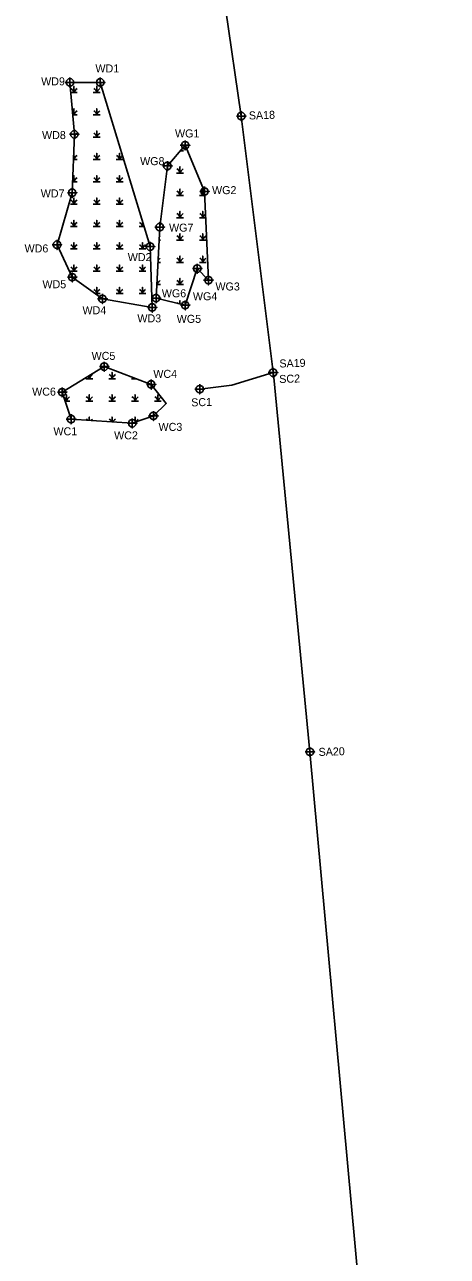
# Model space of a CAD drawing. Extents: x 1616941 to 1621864, y 896903 to 900301.
# Drawn here: x 1619806 to 1620070, y 897710 to 898479 of the extents above; entities that cross this region are included whole.
import ezdxf

# ---------------------------------------------------------------- set-up
doc = ezdxf.new("R2010")
doc.units = 0
for name, color, linetype in [('Exist Hydro Swamp or Marsh', 7, 'Continuous'), ('Sheet Block Revision CELL', 7, 'Continuous'), ('Sheet Layout Plan Border', 7, 'Continuous'), ('Sheet North Arrow Point CELL', 7, 'Continuous'), ('Sheet Plan CELL', 7, 'Continuous'), ('Sheet Plot Border Outside CELL', 7, 'Continuous'), ('Sheet Sticker Exception Certification CELL', 7, 'Continuous')]:
    doc.layers.add(name, color=color, linetype=linetype)

msp = doc.modelspace()

# ---------------------------------------------------------------- linework, layer by layer
at = {"layer": 'Exist Hydro Swamp or Marsh'}
for p, q in [((1619836.65, 898408.67), (1619838.56, 898408.67)), ((1619862.86, 898408.67), (1619863.36, 898408.67)), ((1619903.05, 898400.28), (1619904.89, 898400.28)), ((1619889.69, 898344.5), (1619890.59, 898344.5)), ((1619888.96, 898330.55), (1619890.59, 898330.55))]:
    msp.add_line(p, q, dxfattribs=at)
for points in [[(1619834.55, 898436.56), (1619836.41, 898436.56), (1619836.41, 898440.5), (1619836.41, 898436.56), (1619838.56, 898436.56)], [(1619848.56, 898436.56), (1619850.71, 898436.56), (1619850.71, 898440.5), (1619850.71, 898436.56), (1619852.86, 898436.56)], [(1619835.71, 898422.61), (1619836.41, 898422.61), (1619836.41, 898426.56), (1619836.41, 898422.61), (1619838.56, 898422.61)], [(1619848.56, 898422.61), (1619850.71, 898422.61), (1619850.71, 898426.56), (1619850.71, 898422.61), (1619852.86, 898422.61)], [(1619848.56, 898408.67), (1619850.71, 898408.67), (1619850.71, 898412.61), (1619850.71, 898408.67), (1619852.86, 898408.67)], [(1619836.13, 898394.72), (1619836.41, 898394.72), (1619836.41, 898398.67), (1619836.41, 898394.72), (1619838.56, 898394.72)], [(1619848.56, 898394.72), (1619850.71, 898394.72), (1619850.71, 898398.67), (1619850.71, 898394.72), (1619852.86, 898394.72)], [(1619862.86, 898394.72), (1619865.01, 898394.72), (1619865.01, 898398.67), (1619865.01, 898394.72), (1619867.16, 898394.72)], [(1619835.62, 898380.78), (1619836.41, 898380.78), (1619836.41, 898384.72), (1619836.41, 898380.78), (1619838.56, 898380.78)], [(1619848.56, 898380.78), (1619850.71, 898380.78), (1619850.71, 898384.72), (1619850.71, 898380.78), (1619852.86, 898380.78)], [(1619862.86, 898380.78), (1619865.01, 898380.78), (1619865.01, 898384.72), (1619865.01, 898380.78), (1619867.16, 898380.78)], [(1619900.59, 898386.33), (1619902.74, 898386.33), (1619902.74, 898390.28), (1619902.74, 898386.33), (1619904.89, 898386.33)], [(1619900.59, 898372.39), (1619902.74, 898372.39), (1619902.74, 898376.33), (1619902.74, 898372.39), (1619904.89, 898372.39)], [(1619914.89, 898372.39), (1619917.04, 898372.39), (1619917.04, 898376.33), (1619917.04, 898372.39), (1619918.21, 898372.39)], [(1619834.26, 898366.83), (1619836.41, 898366.83), (1619836.41, 898370.78), (1619836.41, 898366.83), (1619838.56, 898366.83)], [(1619848.56, 898366.83), (1619850.71, 898366.83), (1619850.71, 898370.78), (1619850.71, 898366.83), (1619852.86, 898366.83)], [(1619862.86, 898366.83), (1619865.01, 898366.83), (1619865.01, 898370.78), (1619865.01, 898366.83), (1619867.16, 898366.83)], [(1619900.59, 898358.44), (1619902.74, 898358.44), (1619902.74, 898362.39), (1619902.74, 898358.44), (1619904.89, 898358.44)], [(1619914.89, 898358.44), (1619917.04, 898358.44), (1619917.04, 898362.39), (1619917.04, 898358.44), (1619918.83, 898358.44)], [(1619834.26, 898352.89), (1619836.41, 898352.89), (1619836.41, 898356.83), (1619836.41, 898352.89), (1619838.56, 898352.89)], [(1619848.56, 898352.89), (1619850.71, 898352.89), (1619850.71, 898356.83), (1619850.71, 898352.89), (1619852.86, 898352.89)], [(1619862.86, 898352.89), (1619865.01, 898352.89), (1619865.01, 898356.83), (1619865.01, 898352.89), (1619867.16, 898352.89)], [(1619877.16, 898352.89), (1619879.31, 898352.89), (1619879.31, 898356.11)], [(1619879.31, 898356.11), (1619879.31, 898352.89), (1619880.29, 898352.89)], [(1619900.59, 898344.5), (1619902.74, 898344.5), (1619902.74, 898348.44), (1619902.74, 898344.5), (1619904.89, 898344.5)], [(1619914.89, 898344.5), (1619917.04, 898344.5), (1619917.04, 898348.44), (1619917.04, 898344.5), (1619919.19, 898344.5)], [(1619834.26, 898338.94), (1619836.41, 898338.94), (1619836.41, 898342.89), (1619836.41, 898338.94), (1619838.56, 898338.94)], [(1619848.56, 898338.94), (1619850.71, 898338.94), (1619850.71, 898342.89), (1619850.71, 898338.94), (1619852.86, 898338.94)], [(1619862.86, 898338.94), (1619865.01, 898338.94), (1619865.01, 898342.89), (1619865.01, 898338.94), (1619867.16, 898338.94)], [(1619877.16, 898338.94), (1619879.31, 898338.94), (1619879.31, 898342.89), (1619879.31, 898338.94), (1619881.46, 898338.94)], [(1619834.26, 898325), (1619836.41, 898325), (1619836.41, 898328.94), (1619836.41, 898325), (1619838.56, 898325)], [(1619848.56, 898325), (1619850.71, 898325), (1619850.71, 898328.94), (1619850.71, 898325), (1619852.86, 898325)], [(1619862.86, 898325), (1619865.01, 898325), (1619865.01, 898328.94), (1619865.01, 898325), (1619867.16, 898325)], [(1619877.16, 898325), (1619879.31, 898325), (1619879.31, 898328.94), (1619879.31, 898325), (1619881.46, 898325)], [(1619900.59, 898330.55), (1619902.74, 898330.55), (1619902.74, 898334.5), (1619902.74, 898330.55), (1619904.89, 898330.55)], [(1619914.89, 898330.55), (1619917.04, 898330.55), (1619917.04, 898334.5), (1619917.04, 898330.55), (1619919.19, 898330.55)], [(1619849.71, 898311.05), (1619850.71, 898311.05), (1619850.71, 898315), (1619850.71, 898311.05), (1619852.86, 898311.05)], [(1619862.86, 898311.05), (1619865.01, 898311.05), (1619865.01, 898315), (1619865.01, 898311.05), (1619867.16, 898311.05)], [(1619877.16, 898311.05), (1619879.31, 898311.05), (1619879.31, 898315), (1619879.31, 898311.05), (1619881.46, 898311.05)], [(1619888.23, 898316.61), (1619888.44, 898316.61), (1619888.44, 898320.55), (1619888.44, 898316.61), (1619890.59, 898316.61)], [(1619900.59, 898316.61), (1619902.74, 898316.61), (1619902.74, 898320.55), (1619902.74, 898316.61), (1619904.89, 898316.61)], [(1619902.74, 898304.59), (1619902.74, 898306.61), (1619902.74, 898304.59)], [(1619843.91, 898257.85), (1619846.06, 898257.85), (1619846.06, 898259.7)], [(1619846.06, 898259.7), (1619846.06, 898257.85), (1619848.21, 898257.85)], [(1619858.21, 898257.85), (1619860.36, 898257.85), (1619860.36, 898261.8), (1619860.36, 898257.85), (1619862.51, 898257.85)], [(1619872.51, 898257.85), (1619874.66, 898257.85), (1619874.66, 898258.1)], [(1619874.66, 898258.1), (1619874.66, 898257.85), (1619875.32, 898257.85)], [(1619830.94, 898243.91), (1619831.76, 898243.91), (1619831.76, 898247.85), (1619831.76, 898243.91), (1619833.91, 898243.91)], [(1619843.91, 898243.91), (1619846.06, 898243.91), (1619846.06, 898247.85), (1619846.06, 898243.91), (1619848.21, 898243.91)], [(1619858.21, 898243.91), (1619860.36, 898243.91), (1619860.36, 898247.85), (1619860.36, 898243.91), (1619862.51, 898243.91)], [(1619872.51, 898243.91), (1619874.66, 898243.91), (1619874.66, 898247.85), (1619874.66, 898243.91), (1619876.81, 898243.91)], [(1619886.81, 898243.91), (1619888.96, 898243.91), (1619888.96, 898247.85), (1619888.96, 898243.91), (1619891.11, 898243.91)], [(1619846.06, 898231.84), (1619846.06, 898233.91), (1619846.06, 898231.84)], [(1619860.36, 898230.86), (1619860.36, 898233.91), (1619860.36, 898230.86)], [(1619874.66, 898231.58), (1619874.66, 898233.91), (1619874.66, 898231.58)]]:
    msp.add_lwpolyline(points, dxfattribs=at)
for centre, radius, start, end in [((1619833.34, 898436.33), 3.07, 4.14034, 67.53497), ((1619840.97, 898435.04), 4.81, 122.12745, 161.62219), ((1619847.64, 898436.33), 3.07, 4.14034, 67.53497), ((1619855.27, 898435.04), 4.81, 122.12745, 161.62219), ((1619833.34, 898422.39), 3.07, 4.14034, 44.10069), ((1619840.97, 898421.1), 4.81, 122.12745, 161.62219), ((1619847.64, 898422.39), 3.07, 4.14034, 67.53497), ((1619855.27, 898421.1), 4.81, 122.12745, 161.62219), ((1619840.97, 898407.15), 4.81, 122.12745, 153.42226), ((1619847.64, 898408.44), 3.07, 4.14034, 67.53497), ((1619855.27, 898407.15), 4.81, 122.12745, 161.62219), ((1619833.34, 898394.5), 3.07, 4.14034, 23.20165), ((1619840.97, 898393.21), 4.81, 122.12745, 161.62219), ((1619847.64, 898394.5), 3.07, 4.14034, 67.53497), ((1619855.27, 898393.21), 4.81, 122.12745, 161.62219), ((1619861.95, 898394.5), 3.07, 4.14034, 67.53497), ((1619869.57, 898393.21), 4.81, 124.50854, 161.62219), ((1619840.97, 898379.26), 4.81, 122.12745, 161.62219), ((1619847.64, 898380.55), 3.07, 4.14034, 67.53497), ((1619855.27, 898379.26), 4.81, 122.12745, 161.62219), ((1619861.95, 898380.55), 3.07, 4.14034, 67.53497), ((1619869.57, 898379.26), 4.81, 122.12745, 161.62219), ((1619899.67, 898386.11), 3.07, 4.14034, 67.53497), ((1619907.3, 898384.82), 4.81, 122.12745, 161.62219), ((1619833.34, 898380.55), 3.07, 4.14034, 40.48348), ((1619833.34, 898366.61), 3.07, 4.14034, 67.53497), ((1619840.97, 898365.32), 4.81, 122.12745, 161.62219), ((1619847.64, 898366.61), 3.07, 4.14034, 67.53497), ((1619855.27, 898365.32), 4.81, 122.12745, 161.62219), ((1619861.95, 898366.61), 3.07, 4.14034, 67.53497), ((1619869.57, 898365.32), 4.81, 122.12745, 161.62219), ((1619899.67, 898372.17), 3.07, 4.14034, 67.53497), ((1619907.3, 898370.87), 4.81, 122.12745, 161.62219), ((1619913.97, 898372.17), 3.07, 4.14034, 67.53497), ((1619921.6, 898370.87), 4.81, 136.20709, 161.62219), ((1619899.67, 898358.22), 3.07, 4.14034, 67.53497), ((1619907.3, 898356.93), 4.81, 122.12745, 161.62219), ((1619913.97, 898358.22), 3.07, 4.14034, 67.53497), ((1619921.6, 898356.93), 4.81, 126.67879, 161.62219), ((1619833.34, 898352.66), 3.07, 4.14034, 67.53497), ((1619840.97, 898351.37), 4.81, 122.12745, 161.62219), ((1619847.64, 898352.66), 3.07, 4.14034, 67.53497), ((1619855.27, 898351.37), 4.81, 122.12745, 161.62219), ((1619861.95, 898352.66), 3.07, 4.14034, 67.53497), ((1619869.57, 898351.37), 4.81, 122.12745, 161.62219), ((1619876.25, 898352.66), 3.07, 4.14034, 67.53497), ((1619883.87, 898351.37), 4.81, 145.30096, 161.62219), ((1619893, 898342.98), 4.81, 122.12745, 131.84472), ((1619899.67, 898344.27), 3.07, 4.14034, 67.53497), ((1619907.3, 898342.98), 4.81, 122.12745, 161.62219), ((1619913.97, 898344.27), 3.07, 4.14034, 67.53497), ((1619921.6, 898342.98), 4.81, 122.12745, 161.62219), ((1619833.34, 898338.72), 3.07, 4.14034, 67.53497), ((1619840.97, 898337.43), 4.81, 122.12745, 161.62219), ((1619847.64, 898338.72), 3.07, 4.14034, 67.53497), ((1619855.27, 898337.43), 4.81, 122.12745, 161.62219), ((1619861.95, 898338.72), 3.07, 4.14034, 67.53497), ((1619869.57, 898337.43), 4.81, 122.12745, 161.62219), ((1619876.25, 898338.72), 3.07, 4.14034, 67.53497), ((1619883.87, 898337.43), 4.81, 122.12745, 161.62219), ((1619893, 898329.04), 4.81, 122.12745, 145.88991), ((1619899.67, 898330.33), 3.07, 4.14034, 67.53497), ((1619907.3, 898329.04), 4.81, 122.12745, 161.62219), ((1619913.97, 898330.33), 3.07, 4.14034, 67.53497), ((1619921.6, 898329.04), 4.81, 122.12745, 161.62219), ((1619833.34, 898324.77), 3.07, 4.14034, 67.53497), ((1619840.97, 898323.48), 4.81, 122.12745, 161.62219), ((1619847.64, 898324.77), 3.07, 4.14034, 67.53497), ((1619855.27, 898323.48), 4.81, 122.12745, 161.62219), ((1619861.95, 898324.77), 3.07, 4.14034, 67.53497), ((1619869.57, 898323.48), 4.81, 122.12745, 161.62219), ((1619876.25, 898324.77), 3.07, 4.14034, 67.53497), ((1619883.87, 898323.48), 4.81, 122.12745, 161.62219), ((1619847.64, 898310.83), 3.07, 4.14034, 67.53497), ((1619855.27, 898309.54), 4.81, 122.12745, 161.62219), ((1619861.95, 898310.83), 3.07, 4.14034, 67.53497), ((1619869.57, 898309.54), 4.81, 122.12745, 161.62219), ((1619876.25, 898310.83), 3.07, 4.14034, 67.53497), ((1619883.87, 898309.54), 4.81, 122.12745, 161.62219), ((1619885.37, 898316.38), 3.07, 4.14034, 19.32546), ((1619893, 898315.09), 4.81, 122.12745, 161.62219), ((1619899.67, 898316.38), 3.07, 4.14034, 67.53497), ((1619907.3, 898315.09), 4.81, 122.12745, 161.62219), ((1619899.67, 898302.44), 3.07, 52.45987, 67.53497), ((1619907.3, 898301.15), 4.81, 122.12745, 138.14469), ((1619850.62, 898256.34), 4.81, 122.12745, 161.62219), ((1619857.29, 898257.63), 3.07, 4.14034, 67.53497), ((1619864.92, 898256.34), 4.81, 122.12745, 161.62219), ((1619842.99, 898257.63), 3.07, 4.14034, 34.65397), ((1619871.59, 898257.63), 3.07, 4.14034, 9.10063), ((1619879.22, 898256.34), 4.81, 158.80505, 161.62219), ((1619828.69, 898243.68), 3.07, 4.14034, 62.4002), ((1619836.32, 898242.39), 4.81, 122.12745, 161.62219), ((1619842.99, 898243.68), 3.07, 4.14034, 67.53497), ((1619850.62, 898242.39), 4.81, 122.12745, 161.62219), ((1619857.29, 898243.68), 3.07, 4.14034, 67.53497), ((1619864.92, 898242.39), 4.81, 122.12745, 161.62219), ((1619871.59, 898243.68), 3.07, 4.14034, 67.53497), ((1619879.22, 898242.39), 4.81, 122.12745, 161.62219), ((1619885.89, 898243.68), 3.07, 4.14034, 67.53497), ((1619893.52, 898242.39), 4.81, 122.12745, 161.62219), ((1619842.99, 898229.74), 3.07, 44.55953, 67.53497), ((1619850.62, 898228.45), 4.81, 122.12745, 136.35309), ((1619857.29, 898229.74), 3.07, 21.70782, 67.53497), ((1619864.92, 898228.45), 4.81, 122.12745, 150.18472), ((1619871.59, 898229.74), 3.07, 57.27491, 67.53497), ((1619879.22, 898228.45), 4.81, 122.12745, 149.27571)]:
    msp.add_arc(centre, radius, start, end, dxfattribs=at)
at = {"layer": 'Sheet Block Revision CELL'}
for points in [[(1619834.01, 898442.98), (1619852.94, 898442.98), (1619884.09, 898340.38), (1619885.39, 898302.37), (1619854.29, 898307.77), (1619835.37, 898321.29), (1619825.9, 898341.57), (1619835.37, 898374.02), (1619836.72, 898410.53)], [(1619905.99, 898403.72), (1619918.1, 898374.83), (1619920.58, 898319.43), (1619913.57, 898326.66), (1619906.02, 898303.8), (1619887.79, 898308.19), (1619890.11, 898352.57), (1619894.93, 898390.78)], [(1619834.69, 898232.61), (1619829.11, 898249.44), (1619855.45, 898265.4), (1619884.76, 898254.27), (1619894.23, 898242.45), (1619886.16, 898234.63), (1619872.92, 898230.01)]]:
    msp.add_lwpolyline(points, close=True, dxfattribs=at)
at = {"layer": 'Sheet North Arrow Point CELL'}
for points in [[(1619941.08, 898424.92), (1619941.08, 898418.92), (1619941.08, 898421.92), (1619944.08, 898421.92), (1619938.08, 898421.92)], [(1619960.99, 898264.64), (1619960.99, 898258.64), (1619960.99, 898261.64), (1619963.99, 898261.64), (1619957.99, 898261.64)], [(1619915.11, 898254.34), (1619915.11, 898248.34), (1619915.11, 898251.34), (1619918.11, 898251.34), (1619912.11, 898251.34)], [(1619984.05, 898027.72), (1619984.05, 898021.72), (1619984.05, 898024.72), (1619987.05, 898024.72), (1619981.05, 898024.72)]]:
    msp.add_lwpolyline(points, dxfattribs=at)
for centre in [(1619941.08, 898421.92), (1619960.99, 898261.64), (1619915.11, 898251.34), (1619984.05, 898024.72)]:
    msp.add_circle(centre, 2.34, dxfattribs=at)
at = {"layer": 'Sheet Plan CELL'}
for points in [[(1619834.01, 898445.98), (1619834.01, 898439.98), (1619834.01, 898442.98), (1619837.01, 898442.98), (1619831.01, 898442.98)], [(1619852.94, 898445.98), (1619852.94, 898439.98), (1619852.94, 898442.98), (1619855.94, 898442.98), (1619849.94, 898442.98)], [(1619836.72, 898413.53), (1619836.72, 898407.53), (1619836.72, 898410.53), (1619839.72, 898410.53), (1619833.72, 898410.53)], [(1619905.99, 898406.72), (1619905.99, 898400.72), (1619905.99, 898403.72), (1619908.99, 898403.72), (1619902.99, 898403.72)], [(1619894.93, 898393.78), (1619894.93, 898387.78), (1619894.93, 898390.78), (1619897.93, 898390.78), (1619891.93, 898390.78)], [(1619835.37, 898377.02), (1619835.37, 898371.02), (1619835.37, 898374.02), (1619838.37, 898374.02), (1619832.37, 898374.02)], [(1619918.1, 898377.83), (1619918.1, 898371.83), (1619918.1, 898374.83), (1619921.1, 898374.83), (1619915.1, 898374.83)], [(1619890.11, 898355.57), (1619890.11, 898349.57), (1619890.11, 898352.57), (1619893.11, 898352.57), (1619887.11, 898352.57)], [(1619825.9, 898344.57), (1619825.9, 898338.57), (1619825.9, 898341.57), (1619828.9, 898341.57), (1619822.9, 898341.57)], [(1619884.09, 898343.38), (1619884.09, 898337.38), (1619884.09, 898340.38), (1619887.09, 898340.38), (1619881.09, 898340.38)], [(1619913.57, 898329.66), (1619913.57, 898323.66), (1619913.57, 898326.66), (1619916.57, 898326.66), (1619910.57, 898326.66)], [(1619835.37, 898324.29), (1619835.37, 898318.29), (1619835.37, 898321.29), (1619838.37, 898321.29), (1619832.37, 898321.29)], [(1619920.58, 898322.43), (1619920.58, 898316.43), (1619920.58, 898319.43), (1619923.58, 898319.43), (1619917.58, 898319.43)], [(1619854.29, 898310.77), (1619854.29, 898304.77), (1619854.29, 898307.77), (1619857.29, 898307.77), (1619851.29, 898307.77)], [(1619887.79, 898311.19), (1619887.79, 898305.19), (1619887.79, 898308.19), (1619890.79, 898308.19), (1619884.79, 898308.19)], [(1619906.02, 898306.8), (1619906.02, 898300.8), (1619906.02, 898303.8), (1619909.02, 898303.8), (1619903.02, 898303.8)], [(1619885.39, 898305.37), (1619885.39, 898299.37), (1619885.39, 898302.37), (1619888.39, 898302.37), (1619882.39, 898302.37)], [(1619855.45, 898268.4), (1619855.45, 898262.4), (1619855.45, 898265.4), (1619858.45, 898265.4), (1619852.45, 898265.4)], [(1619829.11, 898252.44), (1619829.11, 898246.44), (1619829.11, 898249.44), (1619832.11, 898249.44), (1619826.11, 898249.44)], [(1619884.76, 898257.27), (1619884.76, 898251.27), (1619884.76, 898254.27), (1619887.76, 898254.27), (1619881.76, 898254.27)], [(1619886.16, 898237.63), (1619886.16, 898231.63), (1619886.16, 898234.63), (1619889.16, 898234.63), (1619883.16, 898234.63)], [(1619834.69, 898235.61), (1619834.69, 898229.61), (1619834.69, 898232.61), (1619837.69, 898232.61), (1619831.69, 898232.61)], [(1619872.92, 898233.01), (1619872.92, 898227.01), (1619872.92, 898230.01), (1619875.92, 898230.01), (1619869.92, 898230.01)]]:
    msp.add_lwpolyline(points, dxfattribs=at)
for centre in [(1619834.01, 898442.98), (1619852.94, 898442.98), (1619836.72, 898410.53), (1619905.99, 898403.72), (1619894.93, 898390.78), (1619835.37, 898374.02), (1619918.1, 898374.83), (1619890.11, 898352.57), (1619825.9, 898341.57), (1619884.09, 898340.38), (1619913.57, 898326.66), (1619835.37, 898321.29), (1619920.58, 898319.43), (1619854.29, 898307.77), (1619887.79, 898308.19), (1619906.02, 898303.8), (1619885.39, 898302.37), (1619855.45, 898265.4), (1619884.76, 898254.27), (1619829.11, 898249.44), (1619886.16, 898234.63), (1619834.69, 898232.61), (1619872.92, 898230.01)]:
    msp.add_circle(centre, 2.34, dxfattribs=at)
at = {"layer": 'Sheet Sticker Exception Certification CELL'}
for points in [[(1619911.6, 898624.59), (1619941.08, 898421.92), (1619961.36, 898258.63), (1619984.05, 898024.72), (1620014.66, 897690.75), (1620015.11, 897611.84), (1620038.35, 897311.26), (1620044.28, 897206.66), (1620046.44, 897152.35), (1620069.97, 896906.34)], [(1619915.11, 898251.34), (1619935.17, 898253.91), (1619960.99, 898261.64)]]:
    msp.add_lwpolyline(points, dxfattribs=at)

# ---------------------------------------------------------------- texts
at = {"layer": 'Sheet Layout Plan Border'}
for s, p in [('SA18', (1619945.91, 898419.78)), ('SA19', (1619965.01, 898264.82)), ('SC2', (1619964.91, 898255.14)), ('SC1', (1619909.87, 898240.5)), ('SA20', (1619989.52, 898022.14))]:
    msp.add_text(s, height=5, rotation=1.75759, dxfattribs=at).set_placement(p)
at = {"layer": 'Sheet Plot Border Outside CELL'}
for s, p in [('WD1', (1619849.9, 898449.2)), ('WD9', (1619815.98, 898441.13)), ('WG1', (1619899.67, 898408.58)), ('WD8', (1619816.52, 898407.57)), ('WG8', (1619877.85, 898391.27)), ('WD7', (1619815.72, 898371.09)), ('WG2', (1619922.83, 898373.16)), ('WG7', (1619895.94, 898349.73)), ('WD6', (1619805.6, 898336.74)), ('WD2', (1619870.13, 898331.3)), ('WD5', (1619816.78, 898314.37)), ('WG6', (1619891.42, 898308.72)), ('WG3', (1619924.96, 898312.98)), ('WG4', (1619910.85, 898306.85)), ('WD4', (1619841.8, 898298.12)), ('WD3', (1619876.14, 898293.06)), ('WG5', (1619900.74, 898292.74)), ('WC5', (1619847.51, 898269.61)), ('WC4', (1619886.11, 898258.38)), ('WC6', (1619810.33, 898247.27)), ('WC3', (1619889.36, 898225.24)), ('WC1', (1619823.66, 898222.48)), ('WC2', (1619861.59, 898219.95))]:
    msp.add_text(s, height=5, dxfattribs=at).set_placement(p)

doc.saveas('drawing.dxf')
